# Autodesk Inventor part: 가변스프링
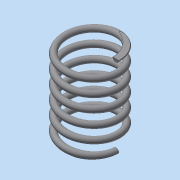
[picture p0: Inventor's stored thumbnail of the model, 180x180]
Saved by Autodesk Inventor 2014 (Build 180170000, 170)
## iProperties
Created: 2023-01
Part Number: 가변스프링
Material: 스테인레스 스틸
Document SubType Name: Modeling
Designer: dg
Density: 8.08 g/cm^3
Appearance: 반연마
Mass: 8.00312 g
Surface Area: 20.0941 cm^2
Volume: 0.990485 cm^3
Author: dg
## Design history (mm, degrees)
sketch "스케치1"
  geometry: L1 (0, 0)-(0, 26.33); L2 (0, 0)-(8.5, 0); L3 (0, 26.33)-(8.5, 26.33); C1 r 1 at (8.5, 0)
  constraints: 6 end point, 1 centre point, 1 coincident, 1 horizontal, 1 perpendicular, 1 vertical, 1 vertical alignment
  dimensions: "d0" = 26.33013 distance of L1.start L1.end (derived); "d1" = 8.5 distance of L1.start L2.end; "d2" = 2 diameter of C1
feature "코일1" pitch "d3" = 10; turns "d5" = 6; dims "d4" = 26.33013 (= d0), "d6" = 0, angle "d7" = 90 deg, angle "d8" = 90 deg, "d9" = 0, "d10" = 0
node "작업 평면1"
node "작업 평면2"
feature "분할1"
feature "분할2"
node "솔리드1"
other parameters: "d11" = 0, "d12" = 0
